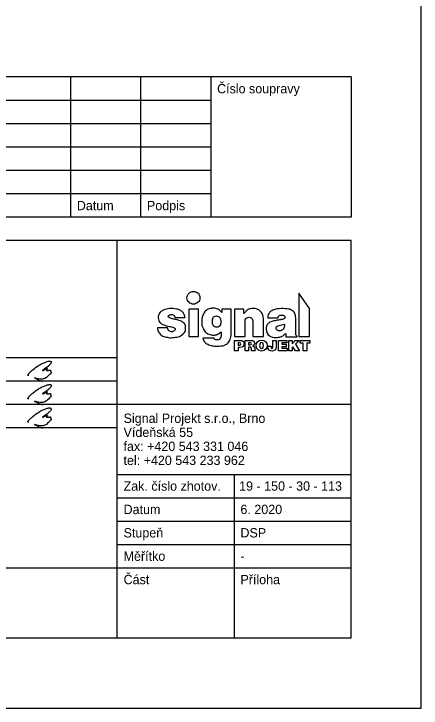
# Model space of a CAD drawing. Extents: x -790471 to -790261, y -990806 to -990509.
# Drawn here: x -790347.7 to -790260.6, y -990805.6 to -990657.1 of the extents above; entities that cross this region are included whole.
import ezdxf

# ---------------------------------------------------------------- set-up
doc = ezdxf.new("R2010")
doc.units = 0
for name, color, linetype in [('Info o rozpiskách', 7, 'Continuous'), ('popis', 7, 'Continuous'), ('Ramečky', 7, 'Continuous'), ('Rámečky-tisk', 7, 'Continuous'), ('Text', 7, 'Continuous')]:
    doc.layers.add(name, color=color, linetype=linetype)

# ---------------------------------------------------------------- blocks, each defined once
blk = doc.blocks.new('Mikulová')
blk.add_open_spline([(-603202, 353349), (-603262, 353345), (-603283, 353370), (-603266, 353420), (-603119, 353582), (-602861, 353814), (-602453, 354093), (-602179, 354214), (-601963, 354293), (-601858, 354309), (-601756, 354307), (-601704, 354283), (-601690, 354237), (-601712, 354169), (-601806, 354054), (-601948, 353930), (-602105, 353821), (-602188, 353766), (-602263, 353721), (-602277, 353710), (-602284, 353692), (-602281, 353685), (-602246, 353684), (-602167, 353722), (-602057, 353777), (-601999, 353810), (-601979, 353824), (-601970, 353844), (-601975, 353858), (-602008, 353853), (-602032, 353839), (-602050, 353822), (-602057, 353805), (-602052, 353791), (-602031, 353783), (-601992, 353787), (-601951, 353784), (-601957, 353767), (-601982, 353749), (-602009, 353730), (-602025, 353711), (-602019, 353693), (-601995, 353684), (-601915, 353688), (-601852, 353696), (-601807, 353702), (-601774, 353703), (-601754, 353700), (-601746, 353685), (-601743, 353667), (-601746, 353622), (-601737, 353604), (-601721, 353579), (-601706, 353549), (-601709, 353516), (-601741, 353477), (-601926, 353311), (-602282, 352945), (-603202, 353349), (-602282, 352945)], degree=3)

msp = doc.modelspace()

# ---------------------------------------------------------------- linework, layer by layer
at = {"layer": 'Info o rozpiskách'}
for points in [[(-790309.25, -990716.41), (-790308.98, -990716.43), (-790308.76, -990716.52), (-790308.54, -990716.65), (-790308.29, -990716.82), (-790308.15, -990717.03), (-790308.03, -990717.27), (-790307.94, -990717.53), (-790307.92, -990717.79), (-790307.94, -990718.05), (-790308.03, -990718.33), (-790308.15, -990718.57), (-790308.29, -990718.74), (-790308.54, -990718.95), (-790308.76, -990719.04), (-790308.98, -990719.13), (-790309.25, -990719.15), (-790309.54, -990719.13), (-790309.79, -990719.04), (-790310.05, -990718.95), (-790310.23, -990718.74), (-790310.4, -990718.57), (-790310.57, -990718.33), (-790310.65, -990718.05), (-790310.7, -990717.79), (-790310.65, -990717.53), (-790310.57, -990717.27), (-790310.4, -990717.03), (-790310.23, -990716.82), (-790310.05, -990716.65), (-790309.79, -990716.52), (-790309.54, -990716.43), (-790309.25, -990716.41)], [(-790300.48, -990726.89), (-790299.41, -990726.89), (-790299, -990726.93), (-790298.7, -990727.08), (-790298.52, -990727.32), (-790298.46, -990727.68), (-790298.65, -990728.2), (-790298.95, -990728.37), (-790299.38, -990728.42), (-790299.75, -990728.42), (-790299.75, -990729.11), (-790300.48, -990729.11), (-790300.48, -990726.89)], [(-790299.75, -990727.4), (-790299.75, -990727.9), (-790299.43, -990727.9), (-790299.25, -990727.85), (-790299.15, -990727.64), (-790299.23, -990727.47), (-790299.54, -990727.4), (-790299.75, -990727.4)], [(-790298.24, -990726.89), (-790297.16, -990726.89), (-790296.67, -990726.93), (-790296.35, -990727.08), (-790296.19, -990727.53), (-790296.3, -990727.88), (-790296.56, -990728.07), (-790296.24, -990728.29), (-790296.19, -990728.67), (-790296.19, -990728.84), (-790296.17, -990729), (-790296.11, -990729.06), (-790296.11, -990729.11), (-790296.86, -990729.11), (-790296.9, -990728.72), (-790297.03, -990728.37), (-790297.18, -990728.35), (-790297.4, -990728.33), (-790297.51, -990728.33), (-790297.51, -990729.11), (-790298.24, -990729.11), (-790298.24, -990726.89)], [(-790297.51, -990727.4), (-790297.51, -990727.85), (-790297.19, -990727.85), (-790296.93, -990727.77), (-790296.88, -990727.64), (-790296.95, -990727.47), (-790297.16, -990727.4), (-790297.51, -990727.4)], [(-790294.73, -990726.84), (-790294.23, -990726.91), (-790293.84, -990727.17), (-790293.63, -990727.55), (-790293.56, -990727.98), (-790293.63, -990728.44), (-790293.85, -990728.82), (-790294.23, -990729.08), (-790294.73, -990729.17), (-790295.25, -990729.08), (-790295.65, -990728.8), (-790295.83, -990728.42), (-790295.91, -990727.98), (-790295.83, -990727.53), (-790295.61, -990727.17), (-790295.23, -990726.91), (-790294.73, -990726.84)], [(-790294.73, -990727.38), (-790294.92, -990727.42), (-790295.05, -990727.53), (-790295.16, -990728), (-790295.05, -990728.48), (-790294.73, -990728.63), (-790294.38, -990728.44), (-790294.28, -990728.03), (-790294.4, -990727.57), (-790294.53, -990727.42), (-790294.73, -990727.38)], [(-790292.33, -990726.89), (-790291.6, -990726.89), (-790291.6, -990728.28), (-790291.67, -990728.7), (-790291.88, -990729), (-790292.46, -990729.17), (-790292.83, -990729.13), (-790293.11, -990728.98), (-790293.29, -990728.7), (-790293.37, -990728.31), (-790293.35, -990728.15), (-790292.7, -990728.15), (-790292.66, -990728.52), (-790292.51, -990728.63), (-790292.38, -990728.56), (-790292.33, -990728.37), (-790292.33, -990726.89)], [(-790291.13, -990726.89), (-790289.32, -990726.89), (-790289.32, -990727.4), (-790290.4, -990727.4), (-790290.4, -990727.73), (-790289.49, -990727.73), (-790289.49, -990728.26), (-790290.4, -990728.26), (-790290.4, -990728.59), (-790289.27, -990728.59), (-790289.27, -990729.11), (-790291.13, -990729.11), (-790291.13, -990726.89)], [(-790288.91, -990726.89), (-790288.16, -990726.89), (-790288.16, -990727.6), (-790287.53, -990726.89), (-790286.67, -990726.89), (-790287.49, -990727.73), (-790286.58, -990729.11), (-790287.46, -990729.11), (-790288, -990728.24), (-790288.16, -990728.41), (-790288.16, -990729.11), (-790288.91, -990729.11), (-790288.91, -990726.89)], [(-790286.47, -990726.89), (-790284.41, -990726.89), (-790284.41, -990727.47), (-790285.07, -990727.47), (-790285.07, -990729.11), (-790285.8, -990729.11), (-790285.8, -990727.47), (-790286.47, -990727.47), (-790286.47, -990726.89)]]:
    msp.add_lwpolyline(points, dxfattribs=at)
at = {"layer": 'popis'}
for points in [[(-790286.77, -990716.82), (-790286.77, -990726.09), (-790284.45, -990726.09), (-790284.45, -990720.07), (-790286.77, -990716.82)], [(-790313.29, -990721.97), (-790311.09, -990721.97), (-790311.15, -990721.78), (-790311.19, -990721.61), (-790311.24, -990721.45), (-790311.32, -990721.28), (-790311.41, -990721.13), (-790311.52, -990720.96), (-790311.63, -990720.81), (-790311.8, -990720.64), (-790311.97, -990720.55), (-790312.17, -990720.44), (-790312.4, -990720.35), (-790312.66, -990720.25), (-790312.94, -990720.2), (-790313.26, -990720.14), (-790313.61, -990720.1), (-790314, -990720.09), (-790314.4, -990720.1), (-790314.77, -990720.14), (-790315.09, -990720.22), (-790315.4, -990720.27), (-790315.66, -990720.37), (-790315.89, -990720.48), (-790316.07, -990720.61), (-790316.26, -990720.74), (-790316.43, -990720.89), (-790316.54, -990721.04), (-790316.65, -990721.19), (-790316.71, -990721.35), (-790316.78, -990721.54), (-790316.82, -990721.71), (-790316.86, -990721.84), (-790316.86, -990722.04), (-790316.8, -990722.34), (-790316.71, -990722.64), (-790316.62, -990722.87), (-790316.43, -990723.11), (-790316.26, -990723.24), (-790316.06, -990723.41), (-790315.81, -990723.52), (-790315.55, -990723.59), (-790315.29, -990723.69), (-790315.03, -990723.76), (-790314.77, -990723.84), (-790314.51, -990723.91), (-790314.25, -990723.95), (-790314.02, -990723.98), (-790313.8, -990724.04), (-790313.59, -990724.13), (-790313.39, -990724.21), (-790313.29, -990724.28), (-790313.22, -990724.38), (-790313.2, -990724.47), (-790313.24, -990724.64), (-790313.29, -990724.71), (-790313.33, -990724.81), (-790313.44, -990724.88), (-790313.57, -990724.95), (-790313.67, -990724.99), (-790313.8, -990725.03), (-790313.93, -990725.03), (-790314.06, -990725.03), (-790314.21, -990724.99), (-790314.38, -990724.94), (-790314.47, -990724.88), (-790314.6, -990724.75), (-790314.69, -990724.64), (-790314.77, -990724.45), (-790314.82, -990724.23), (-790317.01, -990724.23), (-790316.97, -990724.53), (-790316.9, -990724.79), (-790316.8, -990725.01), (-790316.69, -990725.2), (-790316.56, -990725.38), (-790316.41, -990725.55), (-790316.24, -990725.72), (-790316.06, -990725.85), (-790315.83, -990725.96), (-790315.61, -990726.07), (-790315.38, -990726.15), (-790315.14, -990726.22), (-790314.86, -990726.24), (-790314.62, -990726.3), (-790314.38, -990726.32), (-790314.06, -990726.32), (-790313.74, -990726.3), (-790313.43, -990726.3), (-790313.13, -990726.24), (-790312.83, -990726.19), (-790312.55, -990726.13), (-790312.31, -990726.04), (-790312.06, -990725.91), (-790311.86, -990725.81), (-790311.65, -990725.68), (-790311.47, -990725.51), (-790311.34, -990725.37), (-790311.2, -990725.2), (-790311.09, -990725.01), (-790311.02, -990724.79), (-790311, -990724.56), (-790311, -990724.34), (-790311, -990724.28), (-790311, -990724.23), (-790311, -990724.17), (-790311, -990724.11), (-790311, -990724.04), (-790311, -990723.98), (-790311, -990723.95), (-790311, -990723.91), (-790311.02, -990723.67), (-790311.11, -990723.48), (-790311.24, -990723.29), (-790311.39, -990723.16), (-790311.54, -990723.03), (-790311.73, -990722.88), (-790311.9, -990722.79), (-790312.12, -990722.72), (-790312.32, -990722.64), (-790312.55, -990722.57), (-790312.77, -990722.49), (-790312.98, -990722.45), (-790313.22, -990722.4), (-790313.43, -990722.34), (-790313.65, -990722.31), (-790313.84, -990722.25), (-790314.02, -990722.18), (-790314.19, -990722.14), (-790314.32, -990722.06), (-790314.45, -990722.03), (-790314.53, -990721.97), (-790314.64, -990721.89), (-790314.67, -990721.84), (-790314.67, -990721.76), (-790314.67, -990721.69), (-790314.64, -990721.61), (-790314.56, -990721.54), (-790314.49, -990721.5), (-790314.41, -990721.43), (-790314.28, -990721.43), (-790314.13, -990721.39), (-790314, -990721.39), (-790313.85, -990721.39), (-790313.72, -990721.43), (-790313.61, -990721.45), (-790313.5, -990721.5), (-790313.43, -990721.6), (-790313.39, -990721.69), (-790313.31, -990721.8), (-790313.29, -990721.97)], [(-790310.27, -990720.22), (-790310.27, -990726.09), (-790308.18, -990726.09), (-790308.18, -990720.22), (-790310.27, -990720.22)], [(-790303.24, -990720.2), (-790303.24, -990720.92), (-790303.41, -990720.72), (-790303.59, -990720.55), (-790303.8, -990720.38), (-790304.04, -990720.23), (-790304.28, -990720.12), (-790304.51, -990720.07), (-790304.75, -990720.03), (-790305.03, -990720.01), (-790305.29, -990720.03), (-790305.48, -990720.05), (-790305.74, -990720.09), (-790305.93, -990720.18), (-790306.15, -990720.23), (-790306.35, -990720.38), (-790306.58, -990720.5), (-790306.76, -990720.68), (-790306.91, -990720.87), (-790307.06, -990721.11), (-790307.19, -990721.35), (-790307.29, -990721.6), (-790307.4, -990721.91), (-790307.47, -990722.25), (-790307.51, -990722.62), (-790307.51, -990723.01), (-790307.51, -990723.33), (-790307.47, -990723.61), (-790307.4, -990723.87), (-790307.32, -990724.15), (-790307.23, -990724.39), (-790307.1, -990724.64), (-790306.93, -990724.84), (-790306.78, -990725.03), (-790306.62, -990725.2), (-790306.45, -990725.35), (-790306.22, -990725.48), (-790306, -990725.57), (-790305.78, -990725.66), (-790305.53, -990725.72), (-790305.29, -990725.76), (-790305.03, -990725.76), (-790304.81, -990725.76), (-790304.6, -990725.72), (-790304.34, -990725.68), (-790304.12, -990725.59), (-790303.91, -990725.5), (-790303.7, -990725.37), (-790303.56, -990725.23), (-790303.39, -990725.05), (-790303.39, -990725.59), (-790303.39, -990725.98), (-790303.46, -990726.24), (-790303.56, -990726.45), (-790303.63, -990726.6), (-790303.76, -990726.71), (-790303.91, -990726.75), (-790304.08, -990726.8), (-790304.26, -990726.8), (-790304.36, -990726.8), (-790304.49, -990726.78), (-790304.6, -990726.75), (-790304.69, -990726.71), (-790304.75, -990726.63), (-790304.84, -990726.56), (-790304.86, -990726.48), (-790304.9, -990726.39), (-790307.27, -990726.39), (-790307.21, -990726.69), (-790307.1, -990726.89), (-790306.97, -990727.12), (-790306.84, -990727.29), (-790306.67, -990727.49), (-790306.45, -990727.6), (-790306.24, -990727.7), (-790306, -990727.85), (-790305.78, -990727.92), (-790305.53, -990727.98), (-790305.31, -990728.03), (-790305.05, -990728.09), (-790304.84, -990728.11), (-790304.66, -990728.13), (-790304.43, -990728.15), (-790304.26, -990728.15), (-790303.85, -990728.13), (-790303.46, -990728.09), (-790303.09, -990728.03), (-790302.79, -990727.96), (-790302.49, -990727.87), (-790302.23, -990727.73), (-790302.03, -990727.58), (-790301.86, -990727.4), (-790301.69, -990727.19), (-790301.56, -990726.97), (-790301.45, -990726.73), (-790301.35, -990726.45), (-790301.32, -990726.15), (-790301.22, -990725.81), (-790301.22, -990725.46), (-790301.22, -990725.05), (-790301.22, -990720.2), (-790303.24, -990720.2)], [(-790300.5, -990720.22), (-790300.5, -990726.09), (-790298.26, -990726.09), (-790298.26, -990723.09), (-790298.26, -990722.77), (-790298.2, -990722.47), (-790298.11, -990722.31), (-790298.03, -990722.16), (-790297.9, -990722.06), (-790297.75, -990721.99), (-790297.57, -990721.97), (-790297.38, -990721.93), (-790297.19, -990721.97), (-790297.06, -990722.01), (-790296.9, -990722.06), (-790296.8, -990722.18), (-790296.73, -990722.31), (-790296.65, -990722.47), (-790296.62, -990722.73), (-790296.62, -990723), (-790296.62, -990726.09), (-790294.34, -990726.09), (-790294.34, -990722.55), (-790294.34, -990722.23), (-790294.36, -990721.93), (-790294.41, -990721.65), (-790294.51, -990721.39), (-790294.6, -990721.17), (-790294.71, -990720.96), (-790294.88, -990720.79), (-790294.99, -990720.63), (-790295.14, -990720.5), (-790295.31, -990720.37), (-790295.5, -990720.31), (-790295.68, -990720.22), (-790295.91, -990720.14), (-790296.09, -990720.1), (-790296.28, -990720.07), (-790296.5, -990720.07), (-790296.78, -990720.07), (-790297.06, -990720.14), (-790297.31, -990720.18), (-790297.57, -990720.31), (-790297.81, -990720.44), (-790298.05, -990720.63), (-790298.26, -990720.87), (-790298.5, -990721.13), (-790298.5, -990720.22), (-790300.5, -990720.22)], [(-790293.41, -990722.06), (-790291.19, -990722.06), (-790291.17, -990721.89), (-790291.13, -990721.76), (-790291.06, -990721.67), (-790290.96, -990721.6), (-790290.85, -990721.52), (-790290.7, -990721.48), (-790290.57, -990721.48), (-790290.42, -990721.48), (-790290.25, -990721.48), (-790290.09, -990721.5), (-790289.96, -990721.58), (-790289.88, -990721.61), (-790289.81, -990721.69), (-790289.73, -990721.76), (-790289.73, -990721.86), (-790289.69, -990721.95), (-790289.73, -990722.04), (-790289.75, -990722.16), (-790289.84, -990722.23), (-790289.94, -990722.31), (-790290.07, -990722.38), (-790290.25, -990722.42), (-790290.46, -990722.45), (-790290.66, -990722.49), (-790290.89, -990722.51), (-790291.13, -990722.55), (-790291.36, -990722.59), (-790291.6, -990722.62), (-790291.84, -990722.68), (-790292.08, -990722.72), (-790292.29, -990722.79), (-790292.51, -990722.83), (-790292.74, -990722.92), (-790292.96, -990723.03), (-790293.15, -990723.18), (-790293.31, -990723.28), (-790293.44, -990723.42), (-790293.54, -990723.57), (-790293.61, -990723.67), (-790293.67, -990723.84), (-790293.7, -990723.98), (-790293.74, -990724.15), (-790293.76, -990724.3), (-790293.76, -990724.47), (-790293.7, -990724.95), (-790293.56, -990725.35), (-790293.31, -990725.68), (-790293.05, -990725.89), (-790292.74, -990726.07), (-790292.38, -990726.2), (-790292.06, -990726.28), (-790291.73, -990726.3), (-790291.58, -990726.3), (-790291.45, -990726.28), (-790291.3, -990726.28), (-790291.13, -990726.24), (-790291.02, -990726.22), (-790290.85, -990726.2), (-790290.7, -990726.17), (-790290.57, -990726.13), (-790290.44, -990726.06), (-790290.31, -990725.98), (-790290.18, -990725.92), (-790290.03, -990725.83), (-790289.92, -990725.74), (-790289.81, -990725.63), (-790289.66, -990725.51), (-790289.55, -990725.42), (-790289.51, -990726.11), (-790287.12, -990726.11), (-790287.12, -990726.02), (-790287.25, -990725.89), (-790287.31, -990725.79), (-790287.36, -990725.7), (-790287.36, -990725.63), (-790287.4, -990725.51), (-790287.4, -990725.44), (-790287.4, -990725.33), (-790287.4, -990725.18), (-790287.4, -990722.31), (-790287.4, -990722.06), (-790287.46, -990721.82), (-790287.49, -990721.6), (-790287.53, -990721.37), (-790287.59, -990721.19), (-790287.64, -990721.04), (-790287.74, -990720.87), (-790287.9, -990720.7), (-790288.07, -990720.57), (-790288.24, -990720.46), (-790288.46, -990720.35), (-790288.71, -990720.25), (-790288.97, -990720.2), (-790289.3, -990720.16), (-790289.66, -990720.12), (-790290.07, -990720.07), (-790290.53, -990720.09), (-790291.02, -990720.12), (-790291.37, -990720.18), (-790291.73, -990720.23), (-790292.05, -990720.33), (-790292.29, -990720.42), (-790292.53, -990720.55), (-790292.74, -990720.68), (-790292.92, -990720.83), (-790293.05, -990720.98), (-790293.2, -990721.15), (-790293.28, -990721.34), (-790293.31, -990721.48), (-790293.37, -990721.67), (-790293.41, -990721.86), (-790293.41, -990722.06)], [(-790304.39, -990721.65), (-790304.19, -990721.69), (-790303.98, -990721.75), (-790303.8, -990721.84), (-790303.65, -990721.97), (-790303.56, -990722.16), (-790303.48, -990722.36), (-790303.41, -990722.62), (-790303.41, -990722.9), (-790303.41, -990723.14), (-790303.48, -990723.37), (-790303.54, -990723.59), (-790303.63, -990723.76), (-790303.74, -990723.87), (-790303.91, -990724), (-790304.08, -990724.06), (-790304.3, -990724.08), (-790304.53, -990724.06), (-790304.71, -990724), (-790304.9, -990723.87), (-790305.01, -990723.78), (-790305.1, -990723.59), (-790305.2, -990723.42), (-790305.23, -990723.2), (-790305.25, -990722.96), (-790305.23, -990722.7), (-790305.2, -990722.45), (-790305.16, -990722.23), (-790305.09, -990722.03), (-790304.99, -990721.89), (-790304.82, -990721.75), (-790304.64, -990721.69), (-790304.39, -990721.65)], [(-790289.81, -990723.42), (-790289.81, -990723.44), (-790289.81, -990723.5), (-790289.81, -990723.54), (-790289.84, -990723.8), (-790289.86, -990724.06), (-790289.96, -990724.25), (-790290.07, -990724.47), (-790290.22, -990724.64), (-790290.4, -990724.73), (-790290.61, -990724.82), (-790290.81, -990724.88), (-790290.98, -990724.88), (-790291.09, -990724.84), (-790291.21, -990724.79), (-790291.32, -990724.73), (-790291.43, -990724.66), (-790291.52, -990724.56), (-790291.6, -990724.47), (-790291.62, -990724.32), (-790291.58, -990724.08), (-790291.45, -990723.89), (-790291.22, -990723.78), (-790290.98, -990723.7), (-790290.66, -990723.63), (-790290.38, -990723.59), (-790290.09, -990723.5), (-790289.81, -990723.42)]]:
    msp.add_lwpolyline(points, dxfattribs=at)
at = {"layer": 'Ramečky'}
for p, q in [((-790275.59, -990670.55), (-790455.59, -990670.55)), ((-790335.59, -990670.55), (-790335.59, -990700.55)), ((-790320.59, -990670.55), (-790320.59, -990700.55)), ((-790305.59, -990670.55), (-790305.59, -990700.55)), ((-790275.59, -990670.55), (-790275.59, -990700.55)), ((-790305.59, -990675.55), (-790455.59, -990675.55)), ((-790305.59, -990680.55), (-790455.59, -990680.55)), ((-790305.59, -990685.55), (-790455.59, -990685.55)), ((-790305.59, -990690.55), (-790455.59, -990690.55)), ((-790305.59, -990695.55), (-790455.59, -990695.55)), ((-790275.59, -990700.55), (-790455.59, -990700.55)), ((-790275.59, -990705.55), (-790455.59, -990705.55)), ((-790325.59, -990790.55), (-790325.59, -990705.55)), ((-790275.59, -990790.55), (-790275.59, -990705.55)), ((-790455.59, -990730.55), (-790325.59, -990730.55)), ((-790455.59, -990735.55), (-790325.59, -990735.55)), ((-790455.59, -990740.55), (-790325.59, -990740.55)), ((-790455.59, -990745.55), (-790325.59, -990745.55)), ((-790325.59, -990755.55), (-790275.59, -990755.55)), ((-790325.59, -990760.55), (-790275.59, -990760.55)), ((-790325.59, -990765.55), (-790275.59, -990765.55)), ((-790325.59, -990770.55), (-790275.59, -990770.55)), ((-790455.59, -990775.55), (-790275.59, -990775.55)), ((-790455.59, -990790.55), (-790275.59, -990790.55))]:
    msp.add_line(p, q, dxfattribs=at)
for points in [[(-790325.59, -990740.55), (-790275.59, -990740.55)], [(-790300.59, -990755.55), (-790300.59, -990790.55)]]:
    msp.add_lwpolyline(points, dxfattribs=at)
at = {"layer": 'Rámečky-tisk'}
msp.add_lwpolyline([(-790470.59, -990805.55), (-790260.59, -990805.55), (-790260.59, -990508.55)], dxfattribs=at)

# ---------------------------------------------------------------- block references
at = {"xscale": 0.003193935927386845, "yscale": 0.003193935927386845}
for p in [(-788417.91, -991862.98), (-788417.91, -991867.98), (-788417.91, -991872.98)]:
    msp.add_blockref('Mikulová', p, dxfattribs=at)

# ---------------------------------------------------------------- texts
at = {"layer": 'Text'}
for s, p in [('Číslo soupravy', (-790304.24, -990674.05)), ('Podpis', (-790319.24, -990699.05)), ('Datum', (-790334.24, -990699.05)), ('Signal Projekt s.r.o., Brno', (-790324.24, -990744.55)), ('Vídeňská 55', (-790324.24, -990747.55)), ('fax: +420 543 331 046', (-790324.26, -990750.55)), ('tel: +420 543 233 962', (-790324.26, -990753.55)), ('Zak. číslo zhotov.', (-790324.24, -990759.05)), ('19 - 150 - 30 - 113', (-790299.52, -990759.05)), ('Datum', (-790324.24, -990764.05)), ('6. 2020', (-790299.24, -990764.05)), ('Stupeň', (-790324.24, -990769.05)), ('DSP', (-790299.24, -990769.05)), ('Měřítko', (-790324.24, -990774.05)), ('-', (-790299.24, -990774.05)), ('Část', (-790324.24, -990779.05)), ('Příloha', (-790299.24, -990779.05))]:
    msp.add_text(s, height=2, dxfattribs=at).set_placement(p)

doc.saveas('drawing.dxf')
